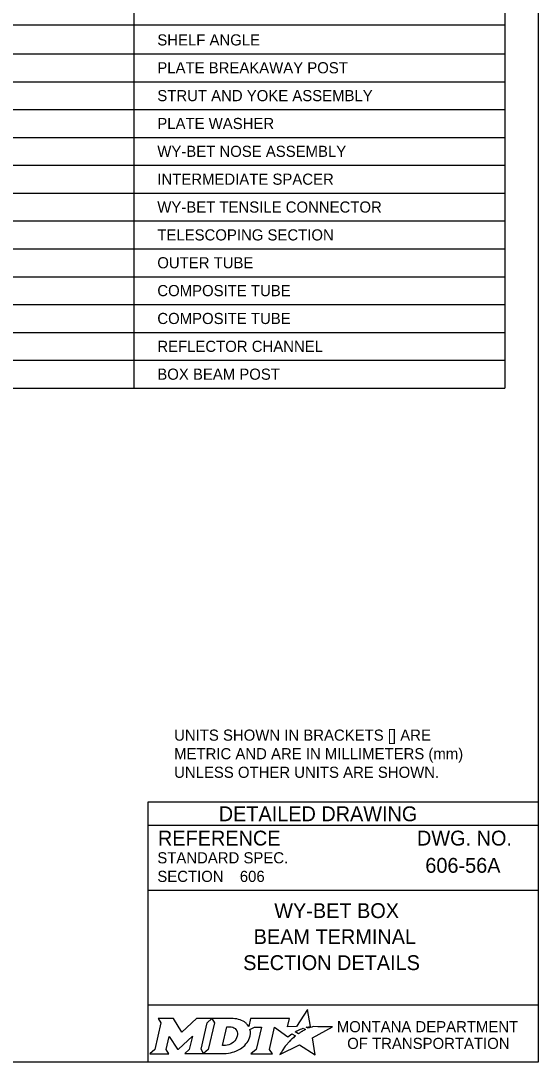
# Model space of a CAD drawing. Extents: x 49991.4 to 50021, y 49987.6 to 50011.4.
# Drawn here: x 50013.97 to 50016.75, y 49987.8 to 49993.41 of the extents above; entities that cross this region are included whole.
import ezdxf

# ---------------------------------------------------------------- set-up
doc = ezdxf.new("R2010")
doc.units = 0
for name, color, linetype in [('Default', 7, 'Continuous'), ('Level 1', 7, 'Continuous'), ('Level 2', 7, 'Continuous'), ('Level 5', 7, 'Continuous')]:
    doc.layers.add(name, color=color, linetype=linetype)

msp = doc.modelspace()

# ---------------------------------------------------------------- linework, layer by layer
at = {"layer": 'Default'}
for points in [[(50014.7056, 49988.0338), (50014.7197, 49988.0104), (50014.6862, 49987.8671), (50014.6605, 49987.8446), (50014.7621, 49987.8446), (50014.7486, 49987.8674), (50014.7648, 49987.9375), (50014.8085, 49987.8685), (50014.8138, 49987.8685), (50014.8889, 49987.938), (50014.8725, 49987.8669), (50014.8478, 49987.8449), (50014.9494, 49987.8449), (50014.9356, 49987.8682), (50014.9688, 49988.0106)], [(50014.9688, 49988.0106), (50014.9941, 49988.0338), (50014.9117, 49988.0338), (50014.8321, 49987.9608), (50014.7876, 49988.0335), (50014.7056, 49988.0338)], [(50015.1077, 49988.0338), (50014.9941, 49988.0338), (50015.0088, 49988.0109), (50014.9749, 49987.8671), (50014.9494, 49987.8449), (50015.06, 49987.8449)], [(50015.5126, 49987.9811), (50015.5023, 49987.9867), (50015.5139, 49987.9895), (50015.5255, 49987.9915), (50015.5081, 49988.0816), (50015.4486, 49987.9903), (50015.4013, 49987.9896), (50015.4116, 49988.0337), (50015.2024, 49988.0338), (50015.1923, 49987.9913), (50015.1865, 49987.9996)], [(50015.1317, 49987.9471), (50015.1305, 49987.939), (50015.1273, 49987.9297), (50015.1231, 49987.9215), (50015.1175, 49987.914), (50015.111, 49987.9071), (50015.1031, 49987.9008), (50015.0948, 49987.8961), (50015.0857, 49987.8922), (50015.0766, 49987.8899), (50015.0674, 49987.889), (50015.0515, 49987.889), (50015.0751, 49987.989), (50015.0911, 49987.989), (50015.0987, 49987.9884), (50015.1063, 49987.9865), (50015.1129, 49987.9835), (50015.119, 49987.9793), (50015.1238, 49987.9743), (50015.1275, 49987.9683), (50015.1302, 49987.9621), (50015.1318, 49987.9547), (50015.1318, 49987.9517), (50015.1317, 49987.9471)], [(50015.1991, 49987.9747), (50015.2237, 49987.9878), (50015.2606, 49987.9878), (50015.232, 49987.8673), (50015.2045, 49987.8446), (50015.3207, 49987.8446), (50015.3037, 49987.8675), (50015.3319, 49987.9877), (50015.4032, 49987.936), (50015.4243, 49987.9511), (50015.444, 49987.9402)], [(50015.3882, 49987.8843), (50015.3729, 49987.8599), (50015.3682, 49987.8524), (50015.3624, 49987.8438), (50015.3601, 49987.8395), (50015.4654, 49987.8926), (50015.5493, 49987.8375), (50015.5362, 49987.9302), (50015.6431, 49987.9886), (50015.5938, 49987.9894), (50015.5637, 49987.9898), (50015.5429, 49987.9901), (50015.5361, 49987.9886), (50015.5312, 49987.9874), (50015.5228, 49987.9851), (50015.5126, 49987.9811)], [(50015.4622, 49987.9535), (50015.4598, 49987.9518), (50015.4415, 49987.9614), (50015.4518, 49987.9671), (50015.4559, 49987.9693), (50015.4645, 49987.9733), (50015.4702, 49987.9759), (50015.4781, 49987.9789), (50015.4854, 49987.9816), (50015.4972, 49987.9742), (50015.4932, 49987.9721), (50015.4886, 49987.9696), (50015.4844, 49987.9674), (50015.4794, 49987.9645), (50015.4775, 49987.9634), (50015.4748, 49987.9618), (50015.4723, 49987.9604), (50015.47, 49987.9588), (50015.4674, 49987.957), (50015.4647, 49987.9552), (50015.4622, 49987.9535)], [(50015.1057, 49987.8522), (50015.1141, 49987.8548), (50015.1271, 49987.8602), (50015.1475, 49987.8712)], [(50015.4021, 49987.9004), (50015.4021, 49987.9004)]]:
    msp.add_lwpolyline(points, dxfattribs=at)
for centre, radius, start, end in [((50015.1308, 49987.9554), 0.0709, 339.5329, 15.8582), ((50015.0868, 49987.9727), 0.1183, 300.9103, 339.1383)]:
    msp.add_arc(centre, radius, start, end, dxfattribs=at)
for centre, major_axis, ratio, start_param, end_param in [((50015.1056, 49987.9864), (0.0834, -0.0037), 0.568097, 0.61298, 1.570796), ((50015.1612, 49987.9937), (0.0361, -0.0295), 0.469099, 1.225588, 1.570796), ((50015.4119, 49987.9106), (-0.0098, -0.0102), 0.016458, 3.141593, 6.279097), ((50015.4329, 49987.9305), (-0.0112, -0.0097), 0.021651, 3.157348, 6.283185), ((50015.3952, 49987.8923), (-0.00694, -0.00806), 0.008222, 0, 3.137361), ((50015.0603, 49987.9932), (0, 0.1484), 0.987302, 3.139398, 3.456847)]:
    msp.add_ellipse(centre, major_axis=major_axis, ratio=ratio, start_param=start_param, end_param=end_param, dxfattribs=at)
at = {"layer": 'Level 1'}
msp.add_lwpolyline([(49999.3835, 49998.9992), (50016.7501, 49998.9992), (50016.7501, 49987.7988), (49999.3835, 49987.7988)], close=True, dxfattribs=at)
at = {"layer": 'Level 2'}
for p, q in [((50016.5707, 49998.8342), (50016.5707, 49991.4286)), ((50014.574, 49998.6342), (50014.574, 49991.4286)), ((50011.3397, 49993.3842), (50016.5707, 49993.3842)), ((50011.3397, 49993.2286), (50016.5707, 49993.2286)), ((50011.3397, 49993.0786), (50016.5707, 49993.0786)), ((50011.3397, 49992.9286), (50016.5707, 49992.9286)), ((50011.3397, 49992.7786), (50016.5707, 49992.7786)), ((50011.3397, 49992.6286), (50016.5707, 49992.6286)), ((50011.3397, 49992.4786), (50016.5707, 49992.4786)), ((50011.3397, 49992.3286), (50016.5707, 49992.3286)), ((50011.3397, 49992.1786), (50016.5707, 49992.1786)), ((50011.3397, 49992.0286), (50016.5707, 49992.0286)), ((50011.3397, 49991.8786), (50016.5707, 49991.8786)), ((50011.3397, 49991.7286), (50016.5707, 49991.7286)), ((50011.3397, 49991.5786), (50016.5707, 49991.5786)), ((50011.3397, 49991.4286), (50016.5707, 49991.4286))]:
    msp.add_line(p, q, dxfattribs=at)
at = {"layer": 'Level 5'}
for p, q in [((50016.7501, 49989.1988), (50014.6501, 49989.1988)), ((50014.6501, 49989.1988), (50014.6501, 49987.7988)), ((50016.7501, 49989.0738), (50014.6501, 49989.0738)), ((50016.3862, 49988.8587), (50016.3862, 49988.8587)), ((50015.1444, 49988.7993), (50015.1444, 49988.7993)), ((50016.7501, 49988.7238), (50014.6501, 49988.7238)), ((50015.7001, 49988.4747), (50015.7001, 49988.4747)), ((50016.7501, 49988.1057), (50014.6501, 49988.1057))]:
    msp.add_line(p, q, dxfattribs=at)

# ---------------------------------------------------------------- texts
at = {"layer": 'Default'}
for s, p in [('MONTANA DEPARTMENT', (50015.6663, 49987.96)), ('OF TRANSPORTATION', (50015.7225, 49987.87))]:
    msp.add_text(s, height=0.06, dxfattribs=at).set_placement(p)
at = {"layer": 'Level 2'}
for s, height, p in [('SHELF ANGLE', 0.06, (50014.7004, 49993.2736)), ('PLATE BREAKAWAY POST', 0.06, (50014.7004, 49993.1236)), ('STRUT AND YOKE ASSEMBLY', 0.06, (50014.7004, 49992.9736)), ('PLATE WASHER', 0.06, (50014.7004, 49992.8236)), ('WY-BET NOSE ASSEMBLY', 0.06, (50014.7004, 49992.6736)), ('INTERMEDIATE SPACER', 0.06, (50014.7004, 49992.5236)), ('WY-BET TENSILE CONNECTOR', 0.06, (50014.7004, 49992.3736)), ('TELESCOPING SECTION', 0.06, (50014.7004, 49992.2236)), ('OUTER TUBE', 0.06, (50014.7004, 49992.0736)), ('COMPOSITE TUBE', 0.06, (50014.7004, 49991.9236)), ('COMPOSITE TUBE', 0.06, (50014.7004, 49991.7736)), ('REFLECTOR CHANNEL', 0.06, (50014.7004, 49991.6236)), ('BOX BEAM POST', 0.06, (50014.7004, 49991.4736)), ('UNITS SHOWN IN BRACKETS [] ARE ', 0.06, (50014.7908, 49989.5299)), ('METRIC AND ARE IN MILLIMETERS (mm) ', 0.06, (50014.7908, 49989.4299)), ('UNLESS OTHER UNITS ARE SHOWN.', 0.06, (50014.7908, 49989.3299)), ('606-56A', 0.08, (50016.1428, 49988.8187)), ('606', 0.06, (50015.1444, 49988.7693)), ('WY-BET BOX', 0.08, (50015.3297, 49988.5747)), ('BEAM TERMINAL', 0.08, (50015.2189, 49988.4347)), ('SECTION DETAILS', 0.08, (50015.1626, 49988.2947))]:
    msp.add_text(s, height=height, dxfattribs=at).set_placement(p)
at = {"layer": 'Level 5'}
for s, height, p in [('DETAILED DRAWING', 0.0799, (50015.0311, 49989.0963)), ('REFERENCE', 0.08, (50014.7037, 49988.9654)), ('DWG. NO.', 0.08, (50016.0979, 49988.9654)), ('STANDARD SPEC.', 0.06, (50014.7004, 49988.8694)), ('SECTION', 0.06, (50014.7004, 49988.7694))]:
    msp.add_text(s, height=height, dxfattribs=at).set_placement(p)

doc.saveas('drawing.dxf')
